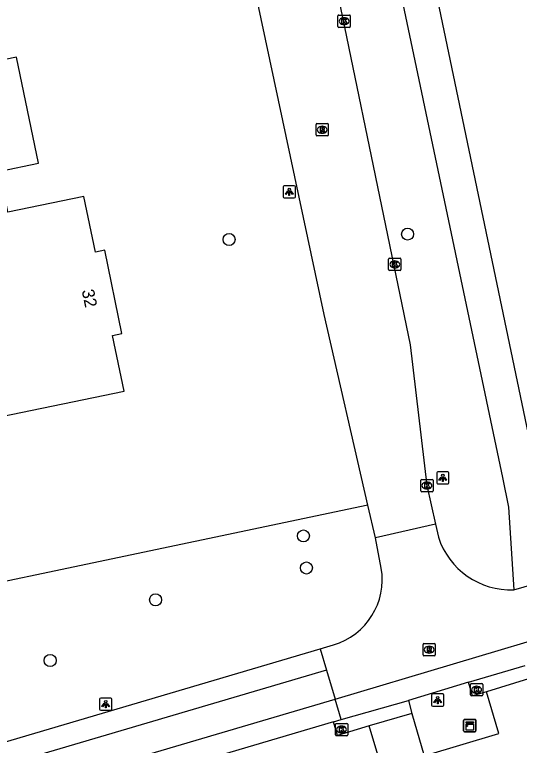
# Model space of a CAD drawing. Extents: x 162417 to 163721, y 384268 to 385416.
# Drawn here: x 163173.2 to 163214.3, y 384656 to 384715.4 of the extents above; entities that cross this region are included whole.
import ezdxf

# ---------------------------------------------------------------- set-up
doc = ezdxf.new("R2010")
doc.units = 0
for name, color, linetype in [('IMGEO_Boom', 7, 'Continuous'), ('IMGEO_Kast', 7, 'Continuous'), ('IMGEO_Kolk', 7, 'Continuous'), ('IMGEO_Lichtpunt', 7, 'Continuous'), ('IMGEO_Loofbos', 7, 'Continuous'), ('IMGEO_Pand', 7, 'Continuous'), ('IMGEO_Pand_nummerreeks', 7, 'Continuous'), ('IMGEO_Rijbaan_lokaal_gesloten', 7, 'Continuous'), ('IMGEO_Rijbaan_lokaal_open', 7, 'Continuous'), ('IMGEO_Rioolput', 7, 'Continuous'), ('IMGEO_Voetpad_open', 7, 'Continuous')]:
    doc.layers.add(name, color=color, linetype=linetype)

msp = doc.modelspace()

# ---------------------------------------------------------------- linework, layer by layer
at = {"layer": 'IMGEO_Boom'}
for centre in [(163205.197, 384697.566), (163190.671, 384697.129), (163196.716, 384673.007), (163196.96, 384670.397), (163184.694, 384667.804), (163176.119, 384662.867)]:
    msp.add_circle(centre, 0.489, dxfattribs=at)
at = {"layer": 'IMGEO_Kast'}
for p, q in [((163209.829, 384658.077), (163210.67, 384658.077)), ((163210.67, 384658.077), (163209.829, 384658.077)), ((163209.754, 384657.152), (163209.754, 384657.993)), ((163209.754, 384657.993), (163209.754, 384657.152)), ((163210.754, 384658.002), (163210.754, 384657.161)), ((163210.754, 384657.161), (163210.754, 384658.002)), ((163210.679, 384657.077), (163209.838, 384657.077)), ((163209.838, 384657.077), (163210.679, 384657.077))]:
    msp.add_line(p, q, dxfattribs=at)
for points in [[(163209.949, 384657.867), (163210.549, 384657.867), (163210.549, 384657.782), (163209.949, 384657.782), (163209.949, 384657.867)], [(163209.949, 384657.692), (163210.549, 384657.692), (163210.549, 384657.203), (163209.949, 384657.203), (163209.949, 384657.692)]]:
    msp.add_lwpolyline(points, dxfattribs=at)
msp.add_circle((163210.033, 384657.541), 0.0377, dxfattribs=at)
for centre, start, end in [((163209.832, 384657.999), 92.4484, 184.28452), ((163209.832, 384657.999), 92.4484, 184.28452), ((163210.676, 384657.999), 2.4484, 94.28452), ((163210.676, 384657.999), 2.4484, 94.28452), ((163209.832, 384657.155), 182.4484, 274.28452), ((163209.832, 384657.155), 182.4484, 274.28452), ((163210.676, 384657.155), 272.4484, 4.28452), ((163210.676, 384657.155), 272.4484, 4.28452)]:
    msp.add_arc(centre, 0.0779, start, end, dxfattribs=at)
at = {"layer": 'IMGEO_Kolk'}
for p, q in [((163199.533, 384714.467), (163199.533, 384715.319)), ((163199.608, 384715.393), (163200.46, 384715.393)), ((163200.021, 384715.173), (163200.046, 384715.173)), ((163200.534, 384715.319), (163200.534, 384714.467)), ((163200.044, 384714.613), (163200.019, 384714.613)), ((163200.46, 384714.393), (163199.608, 384714.393)), ((163203.654, 384694.679), (163203.654, 384695.531)), ((163203.729, 384695.605), (163204.581, 384695.605)), ((163204.655, 384695.531), (163204.655, 384694.679)), ((163204.142, 384695.385), (163204.167, 384695.385)), ((163204.581, 384694.605), (163203.729, 384694.605)), ((163204.165, 384694.825), (163204.14, 384694.825)), ((163206.267, 384676.679), (163206.267, 384677.531)), ((163206.342, 384677.605), (163207.194, 384677.605)), ((163206.755, 384677.385), (163206.78, 384677.385)), ((163207.268, 384677.531), (163207.268, 384676.679)), ((163207.194, 384676.605), (163206.342, 384676.605)), ((163206.778, 384676.825), (163206.753, 384676.825)), ((163210.308, 384660.062), (163210.308, 384660.914)), ((163210.383, 384660.988), (163211.235, 384660.988)), ((163210.796, 384660.768), (163210.821, 384660.768)), ((163211.309, 384660.914), (163211.309, 384660.062)), ((163211.235, 384659.988), (163210.383, 384659.988)), ((163210.819, 384660.208), (163210.794, 384660.208)), ((163199.322, 384656.823), (163199.322, 384657.675)), ((163199.397, 384657.749), (163200.249, 384657.749)), ((163199.81, 384657.529), (163199.835, 384657.529)), ((163200.323, 384657.675), (163200.323, 384656.823)), ((163199.833, 384656.969), (163199.808, 384656.969)), ((163200.249, 384656.749), (163199.397, 384656.749))]:
    msp.add_line(p, q, dxfattribs=at)
for points in [[(163199.533, 384714.467), (163199.533, 384715.319)], [(163199.608, 384715.393), (163200.46, 384715.393)], [(163200.534, 384715.319), (163200.534, 384714.467)], [(163199.854, 384715.093), (163199.977, 384715.093), (163199.977, 384714.942), (163200.107, 384715.093), (163200.271, 384715.093), (163200.125, 384714.942), (163200.278, 384714.693), (163200.126, 384714.693), (163200.041, 384714.857), (163199.977, 384714.79), (163199.977, 384714.693), (163199.854, 384714.693), (163199.854, 384715.093)], [(163200.46, 384714.393), (163199.608, 384714.393)], [(163203.654, 384694.679), (163203.654, 384695.531)], [(163203.729, 384695.605), (163204.581, 384695.605)], [(163204.655, 384695.531), (163204.655, 384694.679)], [(163203.975, 384695.305), (163204.098, 384695.305), (163204.098, 384695.154), (163204.228, 384695.305), (163204.392, 384695.305), (163204.246, 384695.154), (163204.399, 384694.905), (163204.247, 384694.905), (163204.162, 384695.069), (163204.098, 384695.002), (163204.098, 384694.905), (163203.975, 384694.905), (163203.975, 384695.305)], [(163204.581, 384694.605), (163203.729, 384694.605)], [(163206.267, 384676.679), (163206.267, 384677.531)], [(163206.342, 384677.605), (163207.194, 384677.605)], [(163206.588, 384677.305), (163206.711, 384677.305), (163206.711, 384677.154), (163206.841, 384677.305), (163207.005, 384677.305), (163206.859, 384677.154), (163207.012, 384676.905), (163206.86, 384676.905), (163206.775, 384677.069), (163206.711, 384677.002), (163206.711, 384676.905), (163206.588, 384676.905), (163206.588, 384677.305)], [(163207.268, 384677.531), (163207.268, 384676.679)], [(163207.194, 384676.605), (163206.342, 384676.605)], [(163210.308, 384660.062), (163210.308, 384660.914)], [(163210.383, 384660.988), (163211.235, 384660.988)], [(163210.629, 384660.688), (163210.752, 384660.688), (163210.752, 384660.537), (163210.882, 384660.688), (163211.046, 384660.688), (163210.9, 384660.537), (163211.053, 384660.288), (163210.901, 384660.288), (163210.816, 384660.452), (163210.752, 384660.385), (163210.752, 384660.288), (163210.629, 384660.288), (163210.629, 384660.688)], [(163211.309, 384660.914), (163211.309, 384660.062)], [(163211.235, 384659.988), (163210.383, 384659.988)], [(163199.322, 384656.823), (163199.322, 384657.675)], [(163199.397, 384657.749), (163200.249, 384657.749)], [(163200.323, 384657.675), (163200.323, 384656.823)], [(163199.643, 384657.449), (163199.766, 384657.449), (163199.766, 384657.298), (163199.896, 384657.449), (163200.06, 384657.449), (163199.914, 384657.298), (163200.067, 384657.049), (163199.915, 384657.049), (163199.83, 384657.213), (163199.766, 384657.146), (163199.766, 384657.049), (163199.643, 384657.049), (163199.643, 384657.449)], [(163200.249, 384656.749), (163199.397, 384656.749)]]:
    msp.add_lwpolyline(points, dxfattribs=at)
for centre, start, end in [((163199.61, 384715.317), 91.55205, 178.44795), ((163199.61, 384715.317), 91.55205, 178.44795), ((163200.458, 384715.317), 1.55205, 88.44795), ((163200.458, 384715.317), 1.55205, 88.44795), ((163199.61, 384714.469), 181.55205, 268.44795), ((163199.61, 384714.469), 181.55205, 268.44795), ((163200.458, 384714.469), 271.55205, 358.44795), ((163200.458, 384714.469), 271.55205, 358.44795), ((163203.731, 384695.529), 91.55205, 178.44795), ((163203.731, 384695.529), 91.55205, 178.44795), ((163204.579, 384695.529), 1.55205, 88.44795), ((163204.579, 384695.529), 1.55205, 88.44795), ((163203.731, 384694.681), 181.55205, 268.44795), ((163203.731, 384694.681), 181.55205, 268.44795), ((163204.579, 384694.681), 271.55205, 358.44795), ((163204.579, 384694.681), 271.55205, 358.44795), ((163206.344, 384677.529), 91.55205, 178.44795), ((163206.344, 384677.529), 91.55205, 178.44795), ((163207.192, 384677.529), 1.55205, 88.44795), ((163207.192, 384677.529), 1.55205, 88.44795), ((163206.344, 384676.681), 181.55205, 268.44795), ((163206.344, 384676.681), 181.55205, 268.44795), ((163207.192, 384676.681), 271.55205, 358.44795), ((163207.192, 384676.681), 271.55205, 358.44795), ((163210.385, 384660.912), 91.55205, 178.44795), ((163210.385, 384660.912), 91.55205, 178.44795), ((163211.233, 384660.912), 1.55205, 88.44795), ((163211.233, 384660.912), 1.55205, 88.44795), ((163210.385, 384660.064), 181.55205, 268.44795), ((163210.385, 384660.064), 181.55205, 268.44795), ((163211.233, 384660.064), 271.55205, 358.44795), ((163211.233, 384660.064), 271.55205, 358.44795), ((163199.399, 384657.673), 91.55205, 178.44795), ((163199.399, 384657.673), 91.55205, 178.44795), ((163200.247, 384657.673), 1.55205, 88.44795), ((163200.247, 384657.673), 1.55205, 88.44795), ((163199.399, 384656.825), 181.55205, 268.44795), ((163199.399, 384656.825), 181.55205, 268.44795), ((163200.247, 384656.825), 271.55205, 358.44795), ((163200.247, 384656.825), 271.55205, 358.44795)]:
    msp.add_arc(centre, 0.0765, start, end, dxfattribs=at)
for centre, major_axis, ratio, start_param, end_param in [((163200.02, 384714.893), (-0.387, 0.002), 0.722429, 4.712389, 7.853982), ((163200.045, 384714.893), (-0.39, 0.002), 0.717154, 1.570796, 4.712389), ((163204.141, 384695.105), (-0.387, 0.002), 0.722429, 4.712389, 7.853982), ((163204.166, 384695.105), (-0.39, 0.002), 0.717154, 1.570796, 4.712389), ((163206.754, 384677.105), (-0.387, 0.002), 0.722429, 4.712389, 7.853982), ((163206.779, 384677.105), (-0.39, 0.002), 0.717154, 1.570796, 4.712389), ((163210.795, 384660.488), (-0.387, 0.002), 0.722429, 4.712389, 7.853982), ((163210.82, 384660.488), (-0.39, 0.002), 0.717154, 1.570796, 4.712389), ((163199.809, 384657.249), (-0.387, 0.002), 0.722429, 4.712389, 7.853982), ((163199.834, 384657.249), (-0.39, 0.002), 0.717154, 1.570796, 4.712389)]:
    msp.add_ellipse(centre, major_axis=major_axis, ratio=ratio, start_param=start_param, end_param=end_param, dxfattribs=at)
at = {"layer": 'IMGEO_Lichtpunt'}
for p, q in [((163195.97, 384701.509), (163195.162, 384701.509)), ((163195.97, 384701.509), (163195.162, 384701.509)), ((163195.068, 384701.414), (163195.068, 384700.607)), ((163195.068, 384701.414), (163195.068, 384700.607)), ((163196.064, 384700.607), (163196.064, 384701.414)), ((163196.064, 384700.607), (163196.064, 384701.414)), ((163195.162, 384700.513), (163195.97, 384700.513)), ((163195.162, 384700.513), (163195.97, 384700.513)), ((163207.563, 384678.133), (163207.563, 384677.326)), ((163207.563, 384678.133), (163207.563, 384677.326)), ((163208.465, 384678.228), (163207.657, 384678.228)), ((163208.465, 384678.228), (163207.657, 384678.228)), ((163208.559, 384677.326), (163208.559, 384678.133)), ((163208.559, 384677.326), (163208.559, 384678.133)), ((163207.657, 384677.232), (163208.465, 384677.232)), ((163207.657, 384677.232), (163208.465, 384677.232)), ((163207.149, 384660.053), (163207.149, 384659.246)), ((163207.149, 384660.053), (163207.149, 384659.246)), ((163208.051, 384660.148), (163207.243, 384660.148)), ((163208.051, 384660.148), (163207.243, 384660.148)), ((163208.145, 384659.246), (163208.145, 384660.053)), ((163208.145, 384659.246), (163208.145, 384660.053)), ((163180.144, 384659.72), (163180.144, 384658.913)), ((163180.144, 384659.72), (163180.144, 384658.913)), ((163181.046, 384659.815), (163180.238, 384659.815)), ((163181.046, 384659.815), (163180.238, 384659.815)), ((163181.14, 384658.913), (163181.14, 384659.72)), ((163181.14, 384658.913), (163181.14, 384659.72)), ((163180.238, 384658.819), (163181.046, 384658.819)), ((163180.238, 384658.819), (163181.046, 384658.819)), ((163207.243, 384659.152), (163208.051, 384659.152)), ((163207.243, 384659.152), (163208.051, 384659.152))]:
    msp.add_line(p, q, dxfattribs=at)
for points in [[(163195.442, 384701.078), (163195.481, 384701.05), (163195.293, 384700.788), (163195.255, 384700.815), (163195.442, 384701.078)], [(163195.544, 384701.03), (163195.591, 384701.03), (163195.591, 384700.708), (163195.544, 384700.708), (163195.544, 384701.03)], [(163195.654, 384701.05), (163195.692, 384701.077), (163195.879, 384700.815), (163195.84, 384700.787), (163195.654, 384701.05)], [(163207.937, 384677.797), (163207.976, 384677.769), (163207.788, 384677.507), (163207.75, 384677.534), (163207.937, 384677.797)], [(163208.039, 384677.749), (163208.086, 384677.749), (163208.086, 384677.427), (163208.039, 384677.427), (163208.039, 384677.749)], [(163208.149, 384677.769), (163208.187, 384677.796), (163208.374, 384677.534), (163208.335, 384677.506), (163208.149, 384677.769)], [(163180.518, 384659.384), (163180.557, 384659.356), (163180.369, 384659.094), (163180.331, 384659.121), (163180.518, 384659.384)], [(163180.62, 384659.336), (163180.667, 384659.336), (163180.667, 384659.014), (163180.62, 384659.014), (163180.62, 384659.336)], [(163180.73, 384659.356), (163180.768, 384659.383), (163180.955, 384659.121), (163180.916, 384659.093), (163180.73, 384659.356)], [(163207.523, 384659.717), (163207.562, 384659.689), (163207.374, 384659.427), (163207.336, 384659.454), (163207.523, 384659.717)], [(163207.625, 384659.669), (163207.672, 384659.669), (163207.672, 384659.347), (163207.625, 384659.347), (163207.625, 384659.669)], [(163207.735, 384659.689), (163207.773, 384659.716), (163207.96, 384659.454), (163207.921, 384659.426), (163207.735, 384659.689)]]:
    msp.add_lwpolyline(points, dxfattribs=at)
for centre in [(163195.567, 384701.212), (163208.062, 384677.931), (163207.648, 384659.851), (163180.643, 384659.518)]:
    msp.add_circle(centre, 0.0994, dxfattribs=at)
for centre, start, end in [((163195.162, 384701.414), 90, 180), ((163195.162, 384701.414), 90, 180), ((163195.97, 384701.414), 0, 90), ((163195.97, 384701.414), 0, 90), ((163195.162, 384700.607), 180, 270), ((163195.162, 384700.607), 180, 270), ((163195.97, 384700.607), 270, 0), ((163195.97, 384700.607), 270, 360), ((163207.657, 384678.133), 90, 180), ((163207.657, 384678.133), 90, 180), ((163208.465, 384678.133), 0, 90), ((163208.465, 384678.133), 0, 90), ((163207.657, 384677.326), 180, 270), ((163207.657, 384677.326), 180, 270), ((163208.465, 384677.326), 270, 0), ((163208.465, 384677.326), 270, 360), ((163207.243, 384660.053), 90, 180), ((163207.243, 384660.053), 90, 180), ((163208.051, 384660.053), 0, 90), ((163208.051, 384660.053), 0, 90), ((163180.238, 384659.72), 90, 180), ((163180.238, 384659.72), 90, 180), ((163181.046, 384659.72), 0, 90), ((163181.046, 384659.72), 0, 90), ((163180.238, 384658.913), 180, 270), ((163180.238, 384658.913), 180, 270), ((163181.046, 384658.913), 270, 0), ((163181.046, 384658.913), 270, 360), ((163207.243, 384659.246), 180, 270), ((163207.243, 384659.246), 180, 270), ((163208.051, 384659.246), 270, 0), ((163208.051, 384659.246), 270, 360)]:
    msp.add_arc(centre, 0.0946, start, end, dxfattribs=at)
at = {"layer": 'IMGEO_Loofbos'}
msp.add_lwpolyline([(163201.965, 384675.506), (163146.259, 384663.798), (163128.167, 384750), (163118.876, 384794.552), (163174.587, 384805.955)], dxfattribs=at)
at = {"layer": 'IMGEO_Pand'}
msp.add_lwpolyline([(163160.745, 384709.351), (163163.266, 384697.406), (163167.121, 384698.201), (163170.42, 384682.367), (163182.134, 384684.789), (163181.198, 384689.328), (163181.951, 384689.489), (163180.563, 384696.25), (163179.808, 384696.095), (163178.858, 384700.62), (163172.668, 384699.344), (163172.038, 384702.697), (163175.165, 384703.347), (163173.372, 384711.96), (163160.745, 384709.351)], dxfattribs=at)
at = {"layer": 'IMGEO_Rijbaan_lokaal_gesloten'}
for points in [[(163201.965, 384675.506), (163198.408, 384691.02), (163185.859, 384750), (163177.392, 384790.376), (163174.587, 384805.955)], [(163197.565, 384726.517), (163205.399, 384688.547), (163206.768, 384677.105), (163207.46, 384673.956)], [(163202.572, 384672.857), (163201.965, 384675.506)], [(163119.063, 384640.452), (163198.09, 384663.826)], [(163210.145, 384661.119), (163214.749, 384662.457)], [(163198.603, 384662.094), (163119.605, 384638.786)], [(163210.145, 384661.119), (163205.26, 384659.627)], [(163120.305, 384636.428), (163199.311, 384659.719)], [(163199.805, 384658.057), (163199.311, 384659.719)], [(163199.805, 384658.057), (163205.26, 384659.627)], [(163199.174, 384657.875), (163181.582, 384652.661)], [(163199.174, 384657.875), (163199.805, 384658.057)]]:
    msp.add_lwpolyline(points, dxfattribs=at)
at = {"layer": 'IMGEO_Rijbaan_lokaal_open'}
for points in [[(163207.46, 384673.956), (163202.572, 384672.857)], [(163207.46, 384673.956), (163207.703, 384672.895)], [(163203.059, 384670.386), (163202.572, 384672.857)], [(163213.831, 384668.612), (163216.351, 384669.353)], [(163199.311, 384659.719), (163218.569, 384665.465)], [(163198.09, 384663.826), (163199.163, 384664.143)], [(163198.09, 384663.826), (163198.603, 384662.094)], [(163198.603, 384662.094), (163199.311, 384659.719)]]:
    msp.add_lwpolyline(points, dxfattribs=at)
for centre, radius, start, end in [((163213.632, 384674.853), 6.244, 198.27259, 271.82624), ((163197.604, 384669.453), 5.534, 286.35943, 9.70738)]:
    msp.add_arc(centre, radius, start, end, dxfattribs=at)
at = {"layer": 'IMGEO_Rioolput'}
for p, q in [((163197.747, 384705.633), (163197.747, 384706.485)), ((163197.822, 384706.559), (163198.674, 384706.559)), ((163198.235, 384706.339), (163198.26, 384706.339)), ((163198.748, 384706.485), (163198.748, 384705.633)), ((163198.258, 384705.779), (163198.233, 384705.779)), ((163198.674, 384705.559), (163197.822, 384705.559)), ((163206.45, 384663.325), (163206.45, 384664.177)), ((163206.525, 384664.251), (163207.377, 384664.251)), ((163206.938, 384664.031), (163206.963, 384664.031)), ((163207.451, 384664.177), (163207.451, 384663.325)), ((163206.961, 384663.471), (163206.936, 384663.471)), ((163207.377, 384663.251), (163206.525, 384663.251))]:
    msp.add_line(p, q, dxfattribs=at)
for points in [[(163197.747, 384705.633), (163197.747, 384706.485)], [(163197.822, 384706.559), (163198.674, 384706.559)], [(163198.336, 384706.257), (163198.084, 384706.259), (163198.084, 384705.859)], [(163198.748, 384706.485), (163198.748, 384705.633)], [(163198.084, 384705.859), (163198.208, 384705.859), (163198.208, 384706.021), (163198.219, 384706.021)], [(163198.262, 384706.178), (163198.208, 384706.178), (163198.208, 384706.097)], [(163198.208, 384706.097), (163198.26, 384706.097)], [(163198.266, 384705.992), (163198.337, 384705.859), (163198.477, 384705.859), (163198.412, 384705.985)], [(163198.674, 384705.559), (163197.822, 384705.559)], [(163206.45, 384663.325), (163206.45, 384664.177)], [(163206.525, 384664.251), (163207.377, 384664.251)], [(163207.451, 384664.177), (163207.451, 384663.325)], [(163207.039, 384663.949), (163206.787, 384663.951), (163206.787, 384663.551)], [(163206.787, 384663.551), (163206.911, 384663.551), (163206.911, 384663.713), (163206.922, 384663.713)], [(163206.965, 384663.87), (163206.911, 384663.87), (163206.911, 384663.789)], [(163206.911, 384663.789), (163206.963, 384663.789)], [(163206.969, 384663.684), (163207.04, 384663.551), (163207.18, 384663.551), (163207.115, 384663.677)], [(163207.377, 384663.251), (163206.525, 384663.251)]]:
    msp.add_lwpolyline(points, dxfattribs=at)
for centre, radius, start, end in [((163197.824, 384706.483), 0.0765, 91.55205, 178.44795), ((163197.824, 384706.483), 0.0765, 91.55205, 178.44795), ((163198.335, 384706.147), 0.109, 350.36119, 89.41601), ((163198.672, 384706.483), 0.0765, 1.55205, 88.44795), ((163198.672, 384706.483), 0.0765, 1.55205, 88.44795), ((163198.218, 384705.968), 0.0533, 26.02933, 88.69889), ((163198.244, 384706.286), 0.19, 274.7715, 282.96867), ((163198.268, 384706.082), 0.0964, 77.00612, 93.18647), ((163198.282, 384706.139), 0.0378, 276.66336, 79.67722), ((163198.333, 384706.147), 0.112, 277.58423, 350.98172), ((163198.317, 384705.932), 0.108, 29.51342, 73.79051), ((163197.824, 384705.635), 0.0765, 181.55205, 268.44795), ((163197.824, 384705.635), 0.0765, 181.55205, 268.44795), ((163198.672, 384705.635), 0.0765, 271.55205, 358.44795), ((163198.672, 384705.635), 0.0765, 271.55205, 358.44795), ((163206.527, 384664.175), 0.0765, 91.55205, 178.44795), ((163206.527, 384664.175), 0.0765, 91.55205, 178.44795), ((163207.375, 384664.175), 0.0765, 1.55205, 88.44795), ((163207.375, 384664.175), 0.0765, 1.55205, 88.44795), ((163206.921, 384663.66), 0.0533, 26.02933, 88.69889), ((163206.947, 384663.978), 0.19, 274.7715, 282.96867), ((163206.971, 384663.774), 0.0964, 77.00612, 93.18647), ((163206.985, 384663.831), 0.0378, 276.66336, 79.67722), ((163207.038, 384663.839), 0.109, 350.36119, 89.41601), ((163207.036, 384663.839), 0.112, 277.58423, 350.98172), ((163207.02, 384663.624), 0.108, 29.51342, 73.79051), ((163206.527, 384663.327), 0.0765, 181.55205, 268.44795), ((163206.527, 384663.327), 0.0765, 181.55205, 268.44795), ((163207.375, 384663.327), 0.0765, 271.55205, 358.44795), ((163207.375, 384663.327), 0.0765, 271.55205, 358.44795)]:
    msp.add_arc(centre, radius, start, end, dxfattribs=at)
for centre, major_axis, ratio, start_param, end_param in [((163198.234, 384706.059), (-0.387, 0.002), 0.722429, 4.712389, 7.853982), ((163198.259, 384706.059), (-0.39, 0.002), 0.717154, 1.570796, 4.712389), ((163206.937, 384663.751), (-0.387, 0.002), 0.722429, 4.712389, 7.853982), ((163206.962, 384663.751), (-0.39, 0.002), 0.717154, 1.570796, 4.712389)]:
    msp.add_ellipse(centre, major_axis=major_axis, ratio=ratio, start_param=start_param, end_param=end_param, dxfattribs=at)
at = {"layer": 'IMGEO_Voetpad_open'}
for points in [[(163224.144, 384802.92), (163192.437, 384789.411), (163200.664, 384750), (163215.633, 384678.291)], [(163202.624, 384726.782), (163212.911, 384677.77), (163213.416, 384675.345), (163213.831, 384668.612)], [(163211.624, 384660.318), (163210.473, 384659.995), (163210.145, 384661.119)], [(163215.04, 384661.365), (163211.624, 384660.318)], [(163205.547, 384658.562), (163206.554, 384655.12), (163212.618, 384656.917), (163211.624, 384660.318)], [(163205.26, 384659.627), (163205.547, 384658.562)], [(163205.547, 384658.562), (163202.076, 384657.539)], [(163181.899, 384651.654), (163182.949, 384648.117), (163203.103, 384654.103), (163202.076, 384657.539)], [(163202.076, 384657.539), (163199.499, 384656.754), (163199.174, 384657.875)]]:
    msp.add_lwpolyline(points, dxfattribs=at)

# ---------------------------------------------------------------- texts
at = {"layer": 'IMGEO_Pand_nummerreeks'}
msp.add_text('32', height=1, rotation=281.60166, dxfattribs=at).set_placement((163178.683, 384692.976))

doc.saveas('drawing.dxf')
